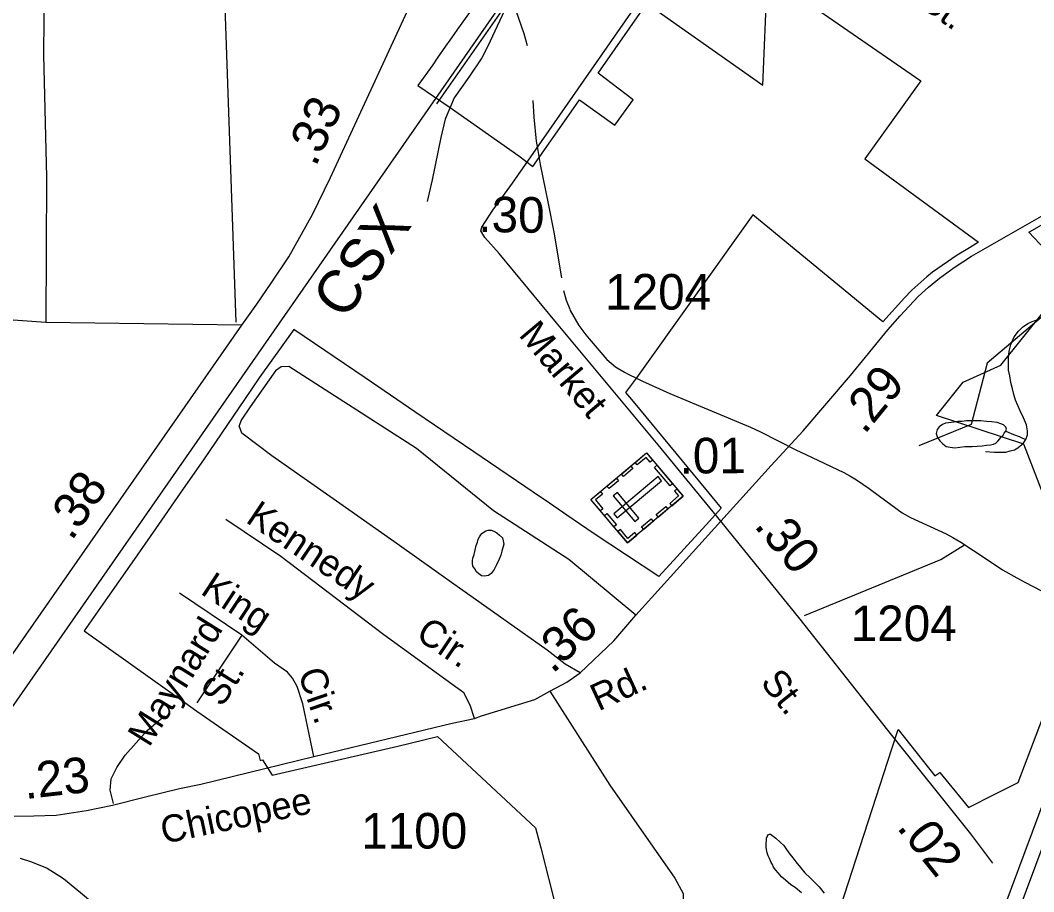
# Model space of a CAD drawing. Extents: x 2082433 to 2279600, y 546599 to 755198.
# Drawn here: x 2131252 to 2134807, y 588272 to 591331 of the extents above; entities that cross this region are included whole.
import ezdxf

# ---------------------------------------------------------------- set-up
doc = ezdxf.new("R2010")
doc.units = 0
for name, color, linetype in [('Exist Boundary Political City Limit New', 7, 'Continuous'), ('Exist Cultural Cemetery CELL', 7, 'Continuous'), ('Exist Hydrographic Misc Water Feature', 7, 'Continuous'), ('Exist Railroad Mainline', 7, 'Continuous'), ('Exist Railroad Mainline Label', 7, 'Continuous'), ('Exist Railroad Spur', 7, 'Continuous'), ('Exist Road Non-System Type 51', 7, 'Continuous'), ('Exist Road Non-System Type 51 Label', 7, 'Continuous'), ('Exist Road Primary Interstate Divided Center Attributed', 7, 'Continuous'), ('Exist Road Primary US Attributed', 7, 'Continuous'), ('Exist Road Primary US Mileage Hundredths English Label', 7, 'Continuous'), ('Exist Road Secondary Mileage Hundredths English Label', 7, 'Continuous'), ('Exist Road Secondary Type 41 Attributed', 7, 'Continuous'), ('Exist Road Secondary Type 51 Attributed', 7, 'Continuous'), ('Exist Road Secondary Type 51 Label', 7, 'Continuous'), ('Exist Road Secondary Type 51 Number Label', 7, 'Continuous'), ('Map Preparation Boundary City Limit Buffer Line', 7, 'Continuous')]:
    doc.layers.add(name, color=color, linetype=linetype)

msp = doc.modelspace()

# ---------------------------------------------------------------- linework, layer by layer
at = {"layer": 'Exist Boundary Political City Limit New'}
for points in [[(2132845.2, 591382.8), (2132800.8, 591320.6), (2132786.5, 591300.7), (2132773, 591281.3), (2132759.2, 591261.7), (2132744.2, 591240.1), (2132715, 591198.3), (2132699, 591175.4), (2132646.8, 591101.9), (2132756.5, 591027.2), (2133000.8, 590855.4), (2133050.5, 590818.1), (2133192.8, 591021.6), (2133214.2, 591052.2), (2133338, 590963.4), (2133402.2, 591052), (2133279.2, 591145.2), (2133450.5, 591390), (2133857.2, 591103.3), (2133872.8, 591467.7)], [(2134053.8, 591365.5), (2134411.2, 591119), (2134215.2, 590844.7), (2134614.2, 590552.1), (2134581.5, 590533.1), (2134538.8, 590506.9), (2134452.8, 590447.4), (2134432.8, 590431.2), (2134380.2, 590383.6), (2134354.2, 590356.8), (2134278.5, 590272.6), (2133822, 590648), (2133414, 590076), (2133375.8, 590024.8), (2133396, 590000), (2133424, 589966.1), (2133634.5, 589711.3), (2133710.8, 589619), (2133670.5, 589573.5), (2133492, 589378.9), (2133266, 589529.1), (2133170, 589594.3), (2133093.2, 589646.4), (2133080.8, 589654.9), (2132843, 589816.6), (2132636.5, 589957.1), (2132573.5, 590000), (2132461.8, 590076), (2132211.5, 590246.3), (2132090.2, 590076), (2132038.8, 590000), (2131897.5, 589792.3), (2131812.8, 589671.5), (2131726.2, 589545.6), (2131644, 589427.2), (2131558.2, 589304.8), (2131477, 589187.6)], [(2134847, 590526.7), (2134790.2, 590587.2), (2134795.2, 590590), (2135076.5, 590752.4)], [(2133921, 587576), (2134309.5, 588774.3), (2134331.8, 588842), (2134461, 588679.2), (2134477.5, 588690.9), (2134578.8, 588568.5), (2134671, 588614.6), (2134752.8, 588655.5), (2134989.8, 589281.1), (2134772.8, 589843.9), (2134466, 589944.1), (2134560.2, 590060.8), (2134692.2, 590120.2), (2134844.2, 590310.2)], [(2131477, 589187.6), (2131707.5, 589023.4), (2131830, 588936.7), (2131871.8, 588906.3), (2132088, 588756.6), (2132093.5, 588733.2), (2132101.8, 588735.1), (2132135.8, 588681.4), (2132576.2, 588783), (2132716.2, 588817.6), (2133060.2, 588496.3), (2133078, 588426), (2133158.8, 588107.5)]]:
    msp.add_lwpolyline(points, dxfattribs=at)
at = {"layer": 'Exist Cultural Cemetery CELL'}
for points in [[(2133382.4, 589496.6), (2133254.3, 589649), (2133449.2, 589812.8), (2133577.3, 589660.4)], [(2133470.6, 589787.5), (2133461.8, 589780.1), (2133447.6, 589796.9), (2133416.7, 589770.9), (2133409.5, 589779.4), (2133449.2, 589812.8)], [(2133401.2, 589757.6), (2133368.1, 589729.7), (2133360.8, 589738.5), (2133393.9, 589766.3)], [(2133531.6, 589697), (2133477, 589762), (2133485.7, 589769.3), (2133540.3, 589704.4)], [(2133350.8, 589715.2), (2133317.6, 589687.3), (2133310.3, 589696.1), (2133343.4, 589723.9)], [(2133334.7, 589598.9), (2133346.7, 589584.6), (2133502, 589715.1), (2133489.9, 589729.4)], [(2133556, 589685.7), (2133547.2, 589678.3), (2133561.4, 589661.5), (2133530.5, 589635.5), (2133537.6, 589627), (2133577.4, 589660.3)], [(2133287.5, 589676.9), (2133294.8, 589668.2), (2133270.1, 589647.5), (2133296.2, 589616.5), (2133287.7, 589609.3), (2133254.3, 589649)], [(2133408.3, 589571.6), (2133422.6, 589583.6), (2133346.8, 589673.8), (2133332.5, 589661.7)], [(2133523.8, 589615.4), (2133490.7, 589587.5), (2133483.4, 589596.2), (2133516.5, 589624.1)], [(2133334.8, 589553.3), (2133301.4, 589593), (2133310.2, 589600.3), (2133343.5, 589560.6)], [(2133472.4, 589572.1), (2133439.2, 589544.3), (2133431.9, 589553), (2133465, 589580.9)], [(2133415.6, 589524.4), (2133408.3, 589533.1), (2133383.7, 589512.4), (2133357.6, 589543.5), (2133349, 589536.3), (2133382.4, 589496.6)]]:
    msp.add_lwpolyline(points, close=True, dxfattribs=at)
at = {"layer": 'Exist Hydrographic Misc Water Feature'}
for p, q in [((2133179.6, 590317.3), (2133181.4, 590312.8)), ((2133973.1, 589824), (2134007.6, 589806.6))]:
    msp.add_line(p, q, dxfattribs=at)
for points in [[(2132972.3, 591421.9), (2132981.5, 591393), (2133018.4, 591284.4), (2133030.3, 591242.9)], [(2133050.8, 591049.9), (2133053.3, 590990.8), (2133062.3, 590906.4), (2133066.4, 590880.7)], [(2133066.4, 590880.7), (2133075.6, 590825.6), (2133103.7, 590688.4)], [(2133103.7, 590688.4), (2133124.4, 590587.4), (2133150.5, 590426.8)], [(2136728.5, 589895), (2136686.7, 589997.6), (2136585.6, 590104.6), (2136377.6, 590177.7), (2135802.5, 590192.6), (2135343.5, 590372.5), (2135184.4, 590398.6), (2134901.4, 590345.3), (2134644.5, 590127.4), (2134587.5, 589912.1), (2134404.4, 589837.1)], [(2133157.4, 590383.3), (2133167.5, 590348.6), (2133179.6, 590317.3)], [(2133181.4, 590312.8), (2133212.2, 590260.3), (2133236.8, 590227.4)], [(2134779.8, 589859.7), (2134786, 589875.8), (2134785.8, 589890.1), (2134781.7, 589911.8), (2134771.6, 589935.6), (2134759.5, 589959.8), (2134751.3, 589979.6), (2134743.3, 589997.5), (2134737.2, 590017.4), (2134732.9, 590037.6), (2134727.3, 590059.5), (2134723.2, 590083.7), (2134718.9, 590103.3), (2134718.9, 590123.6), (2134718.7, 590145.6), (2134721, 590169.6), (2134726.7, 590193.4), (2134738.2, 590219.7), (2134754.2, 590239.6), (2134768.1, 590253.6), (2134786.2, 590267.5), (2134802, 590273.7), (2134825.9, 590281.8)], [(2133236.8, 590227.4), (2133247.7, 590212.7), (2133309.6, 590140.5)], [(2133309.6, 590140.5), (2133340.1, 590115.2), (2133372.1, 590096.6)], [(2133372.1, 590096.6), (2133384.4, 590089.5), (2133415.8, 590073.6)], [(2133372.1, 590096.6), (2133384.4, 590089.5), (2133415.8, 590073.6)], [(2133415.8, 590073.6), (2133434.5, 590064), (2133530.4, 590021.3), (2133814.4, 589902.9), (2133849.5, 589886.7), (2133973.1, 589824)], [(2134709.5, 589889.4), (2134711.7, 589895.6), (2134709.7, 589903.6), (2134701.7, 589911.7), (2134691.6, 589915.3), (2134679.7, 589919.5), (2134659.6, 589921.3), (2134641.6, 589923.2), (2134621.5, 589925.1), (2134603.7, 589924.9), (2134585.8, 589924.8), (2134571.7, 589924.8), (2134555.7, 589922.8), (2134541.7, 589923), (2134527.6, 589920.6), (2134507.9, 589918.7), (2134497.7, 589916.6), (2134487.6, 589912.4), (2134476.1, 589904.4), (2134468.1, 589894.3), (2134465.7, 589880.5), (2134469.8, 589866.5), (2134478, 589854.7), (2134488.2, 589844.6), (2134500.1, 589834.7), (2134513.9, 589832.6), (2134530.1, 589830.6), (2134547.9, 589832.8), (2134566.1, 589834.9), (2134592, 589835), (2134626, 589837.2), (2134641.6, 589839.3), (2134656, 589841.1), (2134666.2, 589843.3), (2134674, 589847.3), (2134681.8, 589853.5), (2134687.9, 589861.5), (2134691.8, 589867.4), (2134700, 589875.5), (2134703.9, 589881.4), (2134709.5, 589889.4)], [(2134637.9, 589817.1), (2134670.1, 589815.5), (2134686.1, 589815.5), (2134709.9, 589815.6), (2134724.2, 589819.5), (2134740.2, 589823.6), (2134751.9, 589829.9), (2134759.9, 589837.6), (2134769.8, 589845.9), (2134779.8, 589859.7)], [(2134709.5, 589889.4), (2134736.1, 589877.7), (2134756, 589869.8), (2134765.9, 589865.9), (2134779.8, 589859.7)], [(2134007.6, 589806.6), (2134141.5, 589744.2), (2134162, 589732.3)], [(2134162, 589732.3), (2134185.4, 589718.5), (2134230.5, 589687.8), (2134266.2, 589661.4)], [(2134266.2, 589661.4), (2134345.3, 589602.6), (2134375.2, 589586.5)], [(2134375.2, 589586.5), (2134500.3, 589528.6), (2134523.7, 589515.2)], [(2132852.1, 589487.5), (2132856.2, 589499.6), (2132858.1, 589509.6), (2132863.8, 589517.6), (2132867.9, 589525.6), (2132871.8, 589529.7), (2132875.9, 589533.7), (2132885.9, 589539.7), (2132893.9, 589541.7), (2132903.8, 589541.8), (2132913.8, 589537.8), (2132923.9, 589531.9), (2132933.9, 589523.9), (2132943.8, 589514), (2132946, 589504), (2132948.1, 589492), (2132946, 589484), (2132942.1, 589468), (2132938, 589454), (2132932.3, 589440), (2132922.4, 589419.9), (2132914.5, 589403.9), (2132904.4, 589389.9), (2132894.6, 589381.8), (2132880.6, 589379.7), (2132870.6, 589381.7), (2132860.5, 589387.7), (2132852.5, 589395.6), (2132846.4, 589405.6), (2132840.4, 589415.5), (2132838.4, 589425.5), (2132838.4, 589433.5), (2132840.4, 589443.5), (2132844.1, 589455.5), (2132852.1, 589487.5)], [(2134523.7, 589515.2), (2134551.4, 589499.1), (2134641, 589440.3)], [(2134641, 589440.3), (2134698.4, 589402.6), (2134748.2, 589374.3)], [(2134748.2, 589374.3), (2134776.3, 589358.5), (2134835, 589328.4)], [(2133993.2, 588268.9), (2133970.9, 588286.8), (2133954.9, 588296.7), (2133936.8, 588312.7), (2133922.9, 588324.6), (2133910.6, 588338.5), (2133902.6, 588348.5), (2133894.6, 588358.5), (2133890.7, 588368.4), (2133886.6, 588374.4), (2133880.7, 588388.4), (2133876.4, 588398.3), (2133872.5, 588408.3), (2133870.4, 588420.3), (2133868.4, 588428.3), (2133868.4, 588440.4), (2133868.4, 588444.3), (2133870.4, 588452.4), (2133870.2, 588460.4), (2133872, 588466.4), (2133876.1, 588472.4), (2133880, 588474.4), (2133884.1, 588474.4), (2133902.2, 588460.5), (2133918.4, 588446.5), (2133930.3, 588434.6), (2133940.3, 588420.6), (2133952.4, 588404.7), (2133962.5, 588390.7), (2133972.7, 588376.8), (2133988.7, 588356.9), (2134004.7, 588338.9), (2134023, 588321), (2134039, 588305.1), (2134055, 588289.1), (2134072.8, 588267.2)]]:
    msp.add_lwpolyline(points, dxfattribs=at)
at = {"layer": 'Exist Railroad Mainline'}
for points in [[(2130988.7, 588583.1), (2133202, 591766.2)], [(2131251.6, 588390.4), (2131291.3, 588377.6), (2131346.9, 588354.5), (2131404.2, 588319.3), (2131471, 588264), (2131551.7, 588196.4), (2131649.9, 588112.4), (2131728.8, 588056.8), (2131768.3, 588030), (2131805.8, 588005.3), (2131839.3, 587984.6), (2131877, 587965.8), (2131928.5, 587942.8), (2132017.7, 587903), (2132116.9, 587863), (2132521.4, 587711.5), (2132994, 587534.1), (2133177.4, 587466.3)]]:
    msp.add_lwpolyline(points, dxfattribs=at)
at = {"layer": 'Exist Railroad Spur'}
for points in [[(2132713, 591038.6), (2132966.8, 591400.7), (2133190.6, 591716.9)], [(2132966.8, 591400.7), (2132892.6, 591240.6), (2132871.9, 591200), (2132825.4, 591131.8), (2132774, 591058.6), (2132743.3, 590984.5), (2132727.5, 590920.2), (2132696.9, 590770.9), (2132679.6, 590694.8)]]:
    msp.add_lwpolyline(points, dxfattribs=at)
at = {"layer": 'Exist Road Non-System Type 51'}
for p, q in [((2131958.3, 591695.8), (2132008, 590271.7)), ((2132029.8, 589172.4), (2131811, 589320.2)), ((2132029.8, 589172.4), (2131872.1, 588935.8))]:
    msp.add_line(p, q, dxfattribs=at)
for points in [[(2131318.9, 591556.9), (2131331.4, 591528.6), (2131337.2, 591516.5), (2131336, 591464.3), (2131334.3, 591210), (2131344.2, 590780.9), (2131342.2, 590270.7)], [(2133412.2, 589243.5), (2133177.1, 589438.5), (2132912.9, 589609.8), (2132641.9, 589827.8), (2132194.1, 590116), (2132167.4, 590114.5), (2132148.2, 590101.1), (2132058.7, 589974.1), (2132026.8, 589928.1), (2132019.9, 589907.8)], [(2133215.9, 589040.3), (2133164.3, 589070.9), (2133100.5, 589119.9), (2132764.8, 589357.6), (2132582.9, 589487.7), (2132373.1, 589635), (2132134.8, 589802.5), (2132029, 589881.6), (2132019.9, 589907.8)], [(2132846.2, 588880.6), (2132830.3, 588927.1), (2132808.6, 588970.6), (2132745.3, 589016.1), (2132527.8, 589174.3), (2132166.8, 589449.3), (2131973.6, 589579.4)], [(2134003.1, 589241.4), (2134482.1, 589438.5), (2134564.9, 589489.7)], [(2132282.6, 588747.1), (2132243.1, 588932), (2132223.3, 588992.3), (2132207.5, 589022), (2132189.8, 589043.3), (2132144.5, 589074.8), (2132029.8, 589172.4)], [(2133110.1, 588976.5), (2133320, 588646.3), (2133548.9, 588320), (2133577.5, 588266.2), (2133578, 588244.4), (2133586.4, 588120.8), (2133587.2, 588001.2), (2133570.9, 587943.9), (2133553.1, 587908.8)], [(2131579.4, 588582), (2131567.5, 588629.3), (2131571.5, 588668.7), (2131591.2, 588708.1), (2131620.7, 588751.5), (2131697.6, 588838.2), (2131758.7, 588889.5)]]:
    msp.add_lwpolyline(points, dxfattribs=at)
at = {"layer": 'Exist Road Primary Interstate Divided Center Attributed'}
for points in [[(2133572.4, 585016.8), (2133731.8, 585446.4), (2134046.9, 586292.6), (2134154.3, 586587.1), (2134345.1, 587093.8), (2134450.9, 587384.3), (2134558, 587677.1), (2134720.4, 588111.8), (2134909.6, 588619.4), (2135080.6, 589076.8), (2135261.3, 589568.1), (2135377, 589874.7), (2135465, 590114.2), (2135535.7, 590283.5), (2135599.7, 590426.9), (2135660.5, 590555.4), (2135767.2, 590753), (2135843.5, 590890.2), (2135928.7, 591028.8), (2136058.4, 591226.9), (2136162.3, 591371.6)], [(2136061, 591334.6), (2135983.6, 591220.5), (2135939.5, 591151.4), (2135859.4, 591033.2), (2135768.2, 590876.7), (2135659.3, 590675), (2135541.2, 590424.1), (2135485.5, 590301.5), (2135429.9, 590157.9), (2135359.3, 589987.7), (2135216.1, 589597.2), (2135116.1, 589330.1), (2135014.5, 589053.4), (2134850, 588609.7), (2134654, 588085.3), (2134535.4, 587761.8), (2134416.1, 587444.7), (2134312, 587159.1), (2134180.1, 586807.3), (2134097.1, 586585.5), (2133955.4, 586204.4), (2133686.3, 585472), (2133605.9, 585261.2), (2133524.4, 585040.6)]]:
    msp.add_lwpolyline(points, dxfattribs=at)
at = {"layer": 'Exist Road Primary US Attributed'}
msp.add_line((2130890.3, 588625.8), (2132029.8, 590260.8), dxfattribs=at)
msp.add_lwpolyline([(2132029.8, 590260.8), (2132081.9, 590334.4), (2132132.8, 590408.1), (2132194.1, 590501.5), (2132277.2, 590649.3), (2132341, 590778.9), (2132717.4, 591595.6), (2132822.2, 591830.9)], dxfattribs=at)
at = {"layer": 'Exist Road Secondary Type 41 Attributed'}
msp.add_lwpolyline([(2134663.9, 588373.1), (2134586.8, 588475.9), (2134296.1, 588840), (2133988.2, 589228.8)], dxfattribs=at)
at = {"layer": 'Exist Road Secondary Type 51 Attributed'}
for points in [[(2133710.2, 589573.5), (2133490.3, 589841.6), (2133132.9, 590269.7), (2132931.7, 590512.9), (2132882.3, 590569.3), (2132868.4, 590592), (2132871.4, 590604.8), (2132910.4, 590665.2), (2132978.6, 590759.1), (2133439.4, 591423.5), (2133638.1, 591711.2), (2133858.6, 592026.5), (2134006.9, 592239.1), (2134142.3, 592427.9), (2134261.9, 592606.9), (2134468.6, 592904.5), (2134674.2, 593203.1), (2134910.2, 593522.2), (2135096.4, 593809.1)], [(2132029.8, 590260.8), (2131342.2, 590270.7), (2130568.8, 590326), (2130469.2, 590328.1), (2130404, 590343.9), (2130360.5, 590373.6), (2130303.1, 590436.8), (2130275.4, 590486.3), (2130243.8, 590577.2), (2130214.1, 590725.5), (2130204.2, 590828.4), (2130200.3, 590937.1), (2130205.3, 590986.2), (2130212.1, 591023.9), (2130250.7, 591172.4), (2130292.2, 591275.2), (2130363.4, 591461.1), (2130391.1, 591548.1), (2130412.9, 591684.5), (2130421.8, 592261.9), (2130431.6, 592451.7)], [(2133710.2, 589573.5), (2133886.6, 589768.1), (2133998.3, 589890.4), (2134165.2, 590084.8), (2134295.4, 590244.4), (2134338.9, 590294.2), (2134402.3, 590361.3), (2134438.2, 590394.6), (2134476.3, 590426.3), (2134528.3, 590463.9), (2134588.6, 590503), (2134842.3, 590648.4), (2135059.6, 590773.5), (2135308.7, 590916.5), (2135338.4, 590933.2)], [(2131231.2, 588537.6), (2131299.4, 588538.5), (2131378.5, 588541.5), (2131484.3, 588557.3), (2131576.2, 588576.1), (2131691.9, 588605.5), (2131810.5, 588635.1), (2131885.2, 588650.3), (2132110.6, 588704.6), (2132282.6, 588747.1), (2132767.9, 588863.7), (2132846.2, 588880.6), (2132870.6, 588889.5), (2133057.8, 588946.7), (2133110.1, 588976.5), (2133169.5, 589007.7), (2133215.9, 589040.3), (2133334.3, 589153.5), (2133412.2, 589243.5), (2133710.2, 589573.5)], [(2133988.2, 589228.8), (2133710.2, 589573.5)]]:
    msp.add_lwpolyline(points, dxfattribs=at)
at = {"layer": 'Map Preparation Boundary City Limit Buffer Line'}
for points in [[(2132845.2, 591382.8), (2132800.8, 591320.6), (2132786.5, 591300.7), (2132773, 591281.3), (2132759.2, 591261.7), (2132744.2, 591240.1), (2132715, 591198.3), (2132699, 591175.4), (2132646.8, 591101.9), (2132756.5, 591027.2), (2133000.8, 590855.4), (2133050.5, 590818.1), (2133192.8, 591021.6), (2133214.2, 591052.2), (2133338, 590963.4), (2133402.2, 591052), (2133279.2, 591145.2), (2133450.5, 591390), (2133857.2, 591103.3), (2133872.8, 591467.7)], [(2134053.8, 591365.5), (2134411.2, 591119), (2134215.2, 590844.7), (2134614.2, 590552.1), (2134581.5, 590533.1), (2134538.8, 590506.9), (2134452.8, 590447.4), (2134432.8, 590431.2), (2134380.2, 590383.6), (2134354.2, 590356.8), (2134278.5, 590272.6), (2133822, 590648), (2133414, 590076), (2133375.8, 590024.8), (2133396, 590000), (2133424, 589966.1), (2133634.5, 589711.3), (2133710.8, 589619), (2133670.5, 589573.5), (2133492, 589378.9), (2133266, 589529.1), (2133170, 589594.3), (2133093.2, 589646.4), (2133080.8, 589654.9), (2132843, 589816.6), (2132636.5, 589957.1), (2132573.5, 590000), (2132461.8, 590076), (2132211.5, 590246.3), (2132090.2, 590076), (2132038.8, 590000), (2131897.5, 589792.3), (2131812.8, 589671.5), (2131726.2, 589545.6), (2131644, 589427.2), (2131558.2, 589304.8), (2131477, 589187.6)], [(2134847, 590526.7), (2134790.2, 590587.2), (2134795.2, 590590), (2135076.5, 590752.4)], [(2133921, 587576), (2134309.5, 588774.3), (2134331.8, 588842), (2134461, 588679.2), (2134477.5, 588690.9), (2134578.8, 588568.5), (2134671, 588614.6), (2134752.8, 588655.5), (2134989.8, 589281.1), (2134772.8, 589843.9), (2134466, 589944.1), (2134560.2, 590060.8), (2134692.2, 590120.2), (2134844.2, 590310.2)], [(2131477, 589187.6), (2131707.5, 589023.4), (2131830, 588936.7), (2131871.8, 588906.3), (2132088, 588756.6), (2132093.5, 588733.2), (2132101.8, 588735.1), (2132135.8, 588681.4), (2132576.2, 588783), (2132716.2, 588817.6), (2133060.2, 588496.3), (2133078, 588426), (2133158.8, 588107.5)]]:
    msp.add_lwpolyline(points, dxfattribs=at)

# ---------------------------------------------------------------- texts
at = {"layer": 'Exist Railroad Mainline Label'}
msp.add_text('CSX', height=150, rotation=54.8502, dxfattribs=at).set_placement((2132390.8, 590275))
at = {"layer": 'Exist Road Non-System Type 51 Label'}
for s, rotation, p in [('St.', 324.3074, (2134401.8, 591383.4)), ('Kennedy', 326.1166, (2132039.2, 589571.4)), ('King', 326.7502, (2131880.9, 589320.2)), ('Maynard', 58.0296, (2131704.2, 588776.4)), ('Cir.', 326.1166, (2132634.9, 589163.8)), ('St.', 58.0296, (2131960.9, 588916.8)), ('Cir.', 288.9091, (2132225.4, 589040.7))]:
    msp.add_text(s, height=95, rotation=rotation, dxfattribs=at).set_placement(p)
at = {"layer": 'Exist Road Primary US Mileage Hundredths English Label'}
for s, rotation, p in [('.33', 65.2521, (2132288.3, 590814)), ('.38', 55.5403, (2131432.4, 589500.8))]:
    msp.add_text(s, height=125, rotation=rotation, dxfattribs=at).set_placement(p)
at = {"layer": 'Exist Road Secondary Mileage Hundredths English Label'}
for s, rotation, p in [('.30', 359.1946, (2132858.6, 590588.2)), ('.29', 50.7458, (2134213.6, 589874.5)), ('.01', 0.4145, (2133565.6, 589740.1)), ('.30', 309.6914, (2133823.4, 589556.1)), ('.36', 43.7161, (2133119.7, 589034.7)), ('.23', 6.5356, (2131269.8, 588597.2)), ('.02', 308.7072, (2134324, 588497.1))]:
    msp.add_text(s, height=125, rotation=rotation, dxfattribs=at).set_placement(p)
at = {"layer": 'Exist Road Secondary Type 51 Label'}
for s, rotation, p in [('Market', 310.0467, (2132997.8, 590225.9)), ('Rd.', 24.7758, (2133280.6, 588904.9)), ('St.', 308.7072, (2133845.7, 589006)), ('Chicopee', 11.6931, (2131755.2, 588440.2))]:
    msp.add_text(s, height=95, rotation=rotation, dxfattribs=at).set_placement(p)
at = {"layer": 'Exist Road Secondary Type 51 Number Label'}
for s, p in [('1204', (2133304.1, 590315.7)), ('1204', (2134165.4, 589151.9)), ('1100', (2132448.4, 588423.8))]:
    msp.add_text(s, height=125, dxfattribs=at).set_placement(p)

doc.saveas('drawing.dxf')
